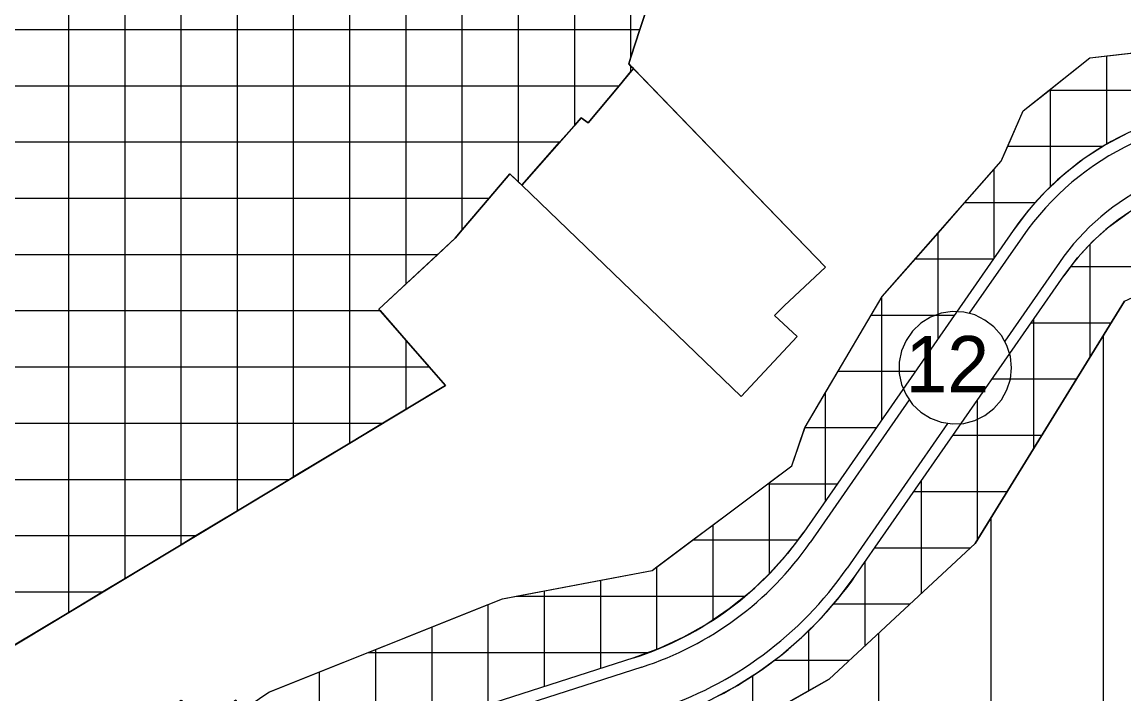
# Model space of a CAD drawing. Extents: x 427903 to 430077, y 4477233 to 4480385.
# Drawn here: x 428612.6 to 428808.6, y 4478205.3 to 4478324.8 of the extents above; entities that cross this region are included whole.
import ezdxf

# ---------------------------------------------------------------- set-up
doc = ezdxf.new("R2010")
doc.units = 0
for name, color, linetype in [('ADAKENARI', 7, 'Continuous'), ('KALDIRIM', 7, 'Continuous'), ('KD_DAIRE', 7, 'Continuous'), ('KD_YGEN', 7, 'Continuous'), ('PL_K_TALI_IS_MRK', 7, 'Continuous'), ('PL_KON_MEV_150', 7, 'Continuous'), ('TR_AZYOGUNKONUT', 7, 'Continuous'), ('TR_TALIISMERK', 7, 'Continuous')]:
    doc.layers.add(name, color=color, linetype=linetype)

msp = doc.modelspace()

# ---------------------------------------------------------------- linework, layer by layer
at = {"layer": 'ADAKENARI'}
for p, q in [((428720.56, 4478317.36), (428723.39, 4478326.12)), ((428802.55, 4478318.43), (428834.94, 4478322.18)), ((428790.72, 4478309), (428802.55, 4478318.43)), ((428786.8, 4478300.04), (428790.72, 4478309)), ((428765.63, 4478276), (428786.8, 4478300.04)), ((428689.68, 4478286.36), (428699.4, 4478297.83)), ((428788.92, 4478287.75), (428751.66, 4478234.1)), ((428676.08, 4478273.76), (428689.68, 4478286.36)), ((428761.02, 4478226.54), (428797.91, 4478279.65)), ((428751.92, 4478252.77), (428765.63, 4478276)), ((428782.14, 4478232.07), (428808.75, 4478275.19)), ((428687.94, 4478260.16), (428676.08, 4478273.76)), ((428607.7, 4478211.85), (428687.94, 4478260.16)), ((428749.55, 4478245.88), (428751.92, 4478252.77)), ((428724.7, 4478227.25), (428749.55, 4478245.88)), ((428756.17, 4478207.92), (428782.14, 4478232.07)), ((428698.11, 4478222.24), (428724.7, 4478227.25)), ((428656.5, 4478205.63), (428698.11, 4478222.24)), ((428721.45, 4478211.74), (428689.92, 4478201.62)), ((428705.03, 4478179.04), (428756.17, 4478207.92)), ((428651.53, 4478202.28), (428656.5, 4478205.63))]:
    msp.add_line(p, q, dxfattribs=at)
for points in [[(428721.36, 4478316.53), (428713.35, 4478306.89), (428712.09, 4478307.75), (428701.51, 4478295.79)], [(428740.52, 4478258.21), (428750.51, 4478268.87), (428746.45, 4478272.6), (428748.19, 4478274.33), (428755.53, 4478281.23), (428720.56, 4478317.36)], [(428740.52, 4478258.21), (428701.51, 4478295.79), (428699.4, 4478297.83)]]:
    msp.add_lwpolyline(points, dxfattribs=at)
for centre, radius, start, end in [((428831.63, 4478258.09), 52, 85.5155, 145.2166), ((428832.95, 4478255.31), 42.66, 85.5155, 145.2166), ((428703.55, 4478267.52), 58.58, 287.792, 325.2166), ((428705.17, 4478265.33), 68, 287.792, 325.2166)]:
    msp.add_arc(centre, radius, start, end, dxfattribs=at)
at = {"layer": 'KALDIRIM'}
for p, q in [((428790.57, 4478286.61), (428781.12, 4478273.01)), ((428797.14, 4478282.04), (428787.43, 4478268.07)), ((428770.42, 4478257.61), (428752.8, 4478232.24)), ((428777.26, 4478253.42), (428759.37, 4478227.68)), ((428722.89, 4478210.11), (428690.36, 4478199.67))]:
    msp.add_line(p, q, dxfattribs=at)
for centre, radius, start, end in [((428831.63, 4478258.09), 50, 85.5155, 145.2166), ((428831.63, 4478258.09), 42, 85.5155, 145.2166), ((428705.17, 4478265.33), 58, 287.792, 325.2166), ((428705.17, 4478265.33), 66, 287.792, 325.2166)]:
    msp.add_arc(centre, radius, start, end, dxfattribs=at)
at = {"layer": 'KD_DAIRE'}
for p, q in [((428776.12, 4478273.01), (428774.22, 4478272.31)), ((428776.12, 4478273.01), (428774.22, 4478272.31)), ((428778.12, 4478273.32), (428776.12, 4478273.01)), ((428778.12, 4478273.32), (428776.12, 4478273.01)), ((428780.14, 4478273.21), (428778.12, 4478273.32)), ((428780.14, 4478273.21), (428778.12, 4478273.32)), ((428782.1, 4478272.71), (428780.14, 4478273.21)), ((428782.1, 4478272.71), (428780.14, 4478273.21)), ((428772.5, 4478271.24), (428771.04, 4478269.84)), ((428772.5, 4478271.24), (428771.04, 4478269.84)), ((428774.22, 4478272.31), (428772.5, 4478271.24)), ((428774.22, 4478272.31), (428772.5, 4478271.24)), ((428783.91, 4478271.81), (428782.1, 4478272.71)), ((428783.91, 4478271.81), (428782.1, 4478272.71)), ((428785.51, 4478270.58), (428783.91, 4478271.81)), ((428785.51, 4478270.58), (428783.91, 4478271.81)), ((428771.04, 4478269.84), (428769.88, 4478268.18)), ((428771.04, 4478269.84), (428769.88, 4478268.18)), ((428786.83, 4478269.04), (428785.51, 4478270.58)), ((428786.83, 4478269.04), (428785.51, 4478270.58)), ((428769.88, 4478268.18), (428769.08, 4478266.32)), ((428769.88, 4478268.18), (428769.08, 4478266.32)), ((428787.81, 4478267.27), (428786.83, 4478269.04)), ((428787.81, 4478267.27), (428786.83, 4478269.04)), ((428788.42, 4478265.34), (428787.81, 4478267.27)), ((428788.42, 4478265.34), (428787.81, 4478267.27)), ((428769.08, 4478266.32), (428768.67, 4478264.34)), ((428769.08, 4478266.32), (428768.67, 4478264.34)), ((428788.62, 4478263.33), (428788.42, 4478265.34)), ((428788.62, 4478263.33), (428788.42, 4478265.34)), ((428768.67, 4478264.34), (428768.67, 4478262.32)), ((428768.67, 4478264.34), (428768.67, 4478262.32)), ((428788.42, 4478261.32), (428788.62, 4478263.33)), ((428788.42, 4478261.32), (428788.62, 4478263.33)), ((428788.62, 4478263.33), (428788.62, 4478263.33)), ((428788.62, 4478263.33), (428788.62, 4478263.33)), ((428768.67, 4478262.32), (428769.08, 4478260.33)), ((428768.67, 4478262.32), (428769.08, 4478260.33)), ((428787.81, 4478259.38), (428788.42, 4478261.32)), ((428787.81, 4478259.38), (428788.42, 4478261.32)), ((428769.08, 4478260.33), (428769.88, 4478258.48)), ((428769.08, 4478260.33), (428769.88, 4478258.48)), ((428786.83, 4478257.62), (428787.81, 4478259.38)), ((428786.83, 4478257.62), (428787.81, 4478259.38)), ((428769.88, 4478258.48), (428771.04, 4478256.81)), ((428769.88, 4478258.48), (428771.04, 4478256.81)), ((428785.51, 4478256.08), (428786.83, 4478257.62)), ((428785.51, 4478256.08), (428786.83, 4478257.62)), ((428771.04, 4478256.81), (428772.5, 4478255.42)), ((428771.04, 4478256.81), (428772.5, 4478255.42)), ((428772.5, 4478255.42), (428774.22, 4478254.35)), ((428772.5, 4478255.42), (428774.22, 4478254.35)), ((428783.91, 4478254.84), (428785.51, 4478256.08)), ((428783.91, 4478254.84), (428785.51, 4478256.08)), ((428774.22, 4478254.35), (428776.12, 4478253.65)), ((428774.22, 4478254.35), (428776.12, 4478253.65)), ((428776.12, 4478253.65), (428778.12, 4478253.34)), ((428776.12, 4478253.65), (428778.12, 4478253.34)), ((428778.12, 4478253.34), (428780.14, 4478253.44)), ((428778.12, 4478253.34), (428780.14, 4478253.44)), ((428780.14, 4478253.44), (428782.1, 4478253.95)), ((428780.14, 4478253.44), (428782.1, 4478253.95)), ((428782.1, 4478253.95), (428783.91, 4478254.84)), ((428782.1, 4478253.95), (428783.91, 4478254.84))]:
    msp.add_line(p, q, dxfattribs=at)
at = {"layer": 'PL_K_TALI_IS_MRK'}
for points in [[(428720.94, 4478318.54), (428722.53, 4478323.48), (428723.39, 4478326.12)], [(428723.39, 4478326.12), (428722.53, 4478323.48)], [(428585.56, 4478161.55), (428622.82, 4478193.45), (428640.91, 4478204.24), (428644.71, 4478199.71), (428650.67, 4478204.26), (428651.53, 4478202.28), (428656.5, 4478205.63), (428698.11, 4478222.24), (428724.7, 4478227.25), (428749.55, 4478245.88), (428751.92, 4478252.77), (428765.63, 4478276), (428786.8, 4478300.04), (428790.72, 4478309), (428802.55, 4478318.43), (428834.94, 4478322.18), (428855.63, 4478318.81), (428872.14, 4478313.5), (428933.8, 4478304.14), (429004.02, 4478272.11)], [(428722.53, 4478323.48), (428720.94, 4478318.54), (428720.56, 4478317.36), (428720.94, 4478316.97), (428721.36, 4478316.53), (428755.53, 4478281.23), (428748.19, 4478274.33), (428746.45, 4478272.6), (428750.51, 4478268.87), (428740.52, 4478258.21), (428701.51, 4478295.79), (428700.94, 4478296.34), (428699.4, 4478297.83), (428695.71, 4478293.48), (428690.94, 4478287.85), (428689.68, 4478286.36), (428686.57, 4478283.48), (428680.94, 4478278.26), (428676.08, 4478273.76), (428676.32, 4478273.48), (428680.94, 4478268.18), (428685.04, 4478263.48), (428687.94, 4478260.16), (428680.94, 4478255.95), (428676.83, 4478253.48), (428670.94, 4478249.93), (428660.94, 4478243.91), (428660.22, 4478243.48), (428650.94, 4478237.89), (428643.62, 4478233.48), (428640.94, 4478231.86), (428630.94, 4478225.84), (428627.01, 4478223.48), (428620.94, 4478219.82), (428610.94, 4478213.8)], [(428610.94, 4478213.8), (428620.94, 4478219.82), (428627.01, 4478223.48), (428630.94, 4478225.84), (428640.94, 4478231.86), (428643.62, 4478233.48), (428650.94, 4478237.89), (428660.22, 4478243.48), (428660.94, 4478243.91), (428670.94, 4478249.93), (428676.83, 4478253.48), (428680.94, 4478255.95), (428687.94, 4478260.16), (428685.04, 4478263.48), (428680.94, 4478268.18), (428676.32, 4478273.48), (428676.08, 4478273.76), (428680.94, 4478278.26), (428686.57, 4478283.48), (428689.68, 4478286.36), (428690.94, 4478287.85), (428695.71, 4478293.48), (428699.4, 4478297.83), (428700.94, 4478296.34), (428701.51, 4478295.79), (428708.31, 4478303.48), (428710.94, 4478306.45), (428712.09, 4478307.75), (428713.35, 4478306.89), (428718.82, 4478313.48), (428720.94, 4478316.03), (428721.36, 4478316.53), (428720.94, 4478316.97), (428720.56, 4478317.36), (428720.94, 4478318.54)], [(428655.56, 4478205), (428656.5, 4478205.63), (428665.56, 4478209.25), (428674.2, 4478212.7), (428675.56, 4478213.24), (428685.56, 4478217.23), (428695.56, 4478221.22), (428698.11, 4478222.24), (428700.53, 4478222.7), (428705.56, 4478223.65), (428715.56, 4478225.53), (428724.7, 4478227.25), (428725.56, 4478227.9), (428731.96, 4478232.7), (428735.56, 4478235.4), (428745.3, 4478242.7), (428745.56, 4478242.9), (428749.55, 4478245.88), (428751.89, 4478252.7), (428751.92, 4478252.77), (428755.56, 4478258.95), (428757.77, 4478262.7), (428763.68, 4478272.7), (428765.56, 4478275.89), (428765.63, 4478276), (428771.52, 4478282.7), (428775.56, 4478287.28), (428780.33, 4478292.7), (428785.56, 4478298.64), (428786.8, 4478300.04), (428787.96, 4478302.7), (428790.72, 4478309), (428795.36, 4478312.7), (428795.56, 4478312.86), (428802.55, 4478318.43), (428805.56, 4478318.78), (428815.56, 4478319.94)], [(428708.31, 4478303.48), (428701.51, 4478295.79), (428740.52, 4478258.21), (428750.51, 4478268.87), (428746.45, 4478272.6), (428748.19, 4478274.33), (428755.53, 4478281.23), (428721.36, 4478316.53), (428720.94, 4478316.03), (428718.82, 4478313.48), (428713.35, 4478306.89), (428712.09, 4478307.75), (428710.94, 4478306.45), (428708.31, 4478303.48)], [(428809.35, 4478305.07), (428805.36, 4478302.96), (428801.57, 4478300.51), (428798, 4478297.75), (428794.69, 4478294.68), (428791.66, 4478291.34), (428788.92, 4478287.75), (428751.66, 4478234.1), (428748.77, 4478230.29), (428745.59, 4478226.72), (428742.12, 4478223.43), (428738.4, 4478220.43), (428734.44, 4478217.75), (428730.28, 4478215.39), (428725.94, 4478213.39), (428721.45, 4478211.74), (428689.92, 4478201.62)], [(428735.09, 4478204.27), (428739.44, 4478206.6), (428743.61, 4478209.24), (428747.58, 4478212.18), (428751.32, 4478215.39), (428754.82, 4478218.87), (428758.06, 4478222.59), (428761.02, 4478226.54), (428797.91, 4478279.65), (428800.37, 4478282.85), (428803.12, 4478285.81), (428806.13, 4478288.5), (428809.39, 4478290.88)], [(428808.75, 4478275.19), (428782.14, 4478232.07), (428756.17, 4478207.92), (428705.03, 4478179.04)]]:
    msp.add_lwpolyline(points, dxfattribs=at)
at = {"layer": 'PL_KON_MEV_150'}
msp.add_lwpolyline([(428917.5, 4478262.42), (428936.22, 4478235.59), (428952.23, 4478189.67), (428913.06, 4478170.27), (428903.17, 4478189.83), (428868.79, 4478175.38), (428861.18, 4478187.2), (428842.96, 4478177.3), (428835.68, 4478188.79), (428792.13, 4478162.34), (428775.21, 4478183.31), (428756.95, 4478169.39), (428745.68, 4478184.6), (428716.29, 4478165.07), (428705, 4478178.94), (428705.03, 4478179.04), (428756.17, 4478207.92), (428782.14, 4478232.07), (428808.75, 4478275.19), (428825.08, 4478282.72), (428861.7, 4478285.08), (428887.4, 4478280.32)], close=True, dxfattribs=at)
at = {"layer": 'TR_AZYOGUNKONUT'}
for p, q in [((428805, 4478170.16), (428805, 4478269.12)), ((428785, 4478171.17), (428785, 4478236.71)), ((428765, 4478175.53), (428765, 4478216.14))]:
    msp.add_line(p, q, dxfattribs=at)
at = {"layer": 'TR_TALIISMERK'}
for p, q in [((428720.94, 4478318.54), (428720.94, 4478427.11)), ((428710.94, 4478306.45), (428710.94, 4478421.21)), ((428700.94, 4478296.34), (428700.94, 4478414.79)), ((428690.94, 4478287.85), (428690.94, 4478407.98)), ((428680.94, 4478278.26), (428680.94, 4478401.14)), ((428670.94, 4478249.93), (428670.94, 4478394.29)), ((428660.94, 4478243.91), (428660.94, 4478387.55)), ((428650.94, 4478237.89), (428650.94, 4478381.81)), ((428640.94, 4478231.86), (428640.94, 4478377.31)), ((428630.94, 4478225.84), (428630.94, 4478373.99)), ((428620.94, 4478219.82), (428620.94, 4478371.62)), ((428518.79, 4478323.48), (428722.53, 4478323.48)), ((428805.56, 4478303.07), (428805.56, 4478318.78)), ((428720.94, 4478316.03), (428720.94, 4478316.97)), ((428513.83, 4478313.48), (428718.82, 4478313.48)), ((428795.36, 4478312.7), (428877.41, 4478312.7)), ((428795.56, 4478295.49), (428795.56, 4478312.86)), ((428508.86, 4478303.48), (428708.31, 4478303.48)), ((428787.96, 4478302.7), (428804.95, 4478302.7)), ((428785.56, 4478282.91), (428785.56, 4478298.64)), ((428503.89, 4478293.48), (428695.71, 4478293.48)), ((428780.33, 4478292.7), (428792.89, 4478292.7)), ((428775.56, 4478268.51), (428775.56, 4478287.28)), ((428802.59, 4478265.2), (428802.59, 4478285.24)), ((428498.69, 4478283.48), (428686.57, 4478283.48)), ((428771.52, 4478282.7), (428785.41, 4478282.7)), ((428799.2, 4478281.33), (428822.07, 4478281.33)), ((428765.56, 4478254.12), (428765.56, 4478275.89)), ((428492.58, 4478273.48), (428676.32, 4478273.48)), ((428763.68, 4478272.7), (428778.47, 4478272.7)), ((428792.13, 4478271.33), (428806.37, 4478271.33)), ((428792.59, 4478249), (428792.59, 4478271.99)), ((428680.94, 4478255.95), (428680.94, 4478268.18)), ((428485.49, 4478263.48), (428685.04, 4478263.48)), ((428757.77, 4478262.7), (428771.52, 4478262.7)), ((428785.18, 4478261.33), (428800.2, 4478261.33)), ((428755.56, 4478239.72), (428755.56, 4478258.95)), ((428782.59, 4478232.79), (428782.59, 4478257.59)), ((428477.13, 4478253.48), (428676.83, 4478253.48)), ((428751.89, 4478252.7), (428764.58, 4478252.7)), ((428778.24, 4478251.33), (428794.02, 4478251.33)), ((428467.37, 4478243.48), (428660.22, 4478243.48)), ((428745.3, 4478242.7), (428757.63, 4478242.7)), ((428745.56, 4478226.7), (428745.56, 4478242.9)), ((428772.59, 4478223.19), (428772.59, 4478243.2)), ((428771.29, 4478241.33), (428787.85, 4478241.33)), ((428735.56, 4478218.51), (428735.56, 4478235.4)), ((428455.86, 4478233.48), (428643.62, 4478233.48)), ((428731.96, 4478232.7), (428750.6, 4478232.7)), ((428764.34, 4478231.33), (428781.34, 4478231.33)), ((428725.56, 4478213.25), (428725.56, 4478227.9)), ((428762.59, 4478213.89), (428762.59, 4478228.8)), ((428715.56, 4478209.85), (428715.56, 4478225.53)), ((428444.01, 4478223.48), (428627.01, 4478223.48)), ((428700.53, 4478222.7), (428741.21, 4478222.7)), ((428705.56, 4478206.64), (428705.56, 4478223.65)), ((428695.56, 4478203.44), (428695.56, 4478221.22)), ((428756.96, 4478221.33), (428770.58, 4478221.33)), ((428685.56, 4478200.3), (428685.56, 4478217.23)), ((428752.59, 4478205.9), (428752.59, 4478216.65)), ((428674.2, 4478212.7), (428724.05, 4478212.7)), ((428675.56, 4478197.68), (428675.56, 4478213.24)), ((428746.43, 4478211.33), (428759.83, 4478211.33)), ((428665.56, 4478195.67), (428665.56, 4478209.25)), ((428742.59, 4478200.25), (428742.59, 4478208.59))]:
    msp.add_line(p, q, dxfattribs=at)
for points in [[(428723.39, 4478326.12), (428722.53, 4478323.48)], [(428722.53, 4478323.48), (428720.94, 4478318.54), (428720.56, 4478317.36), (428720.94, 4478316.97), (428721.36, 4478316.53), (428755.53, 4478281.23), (428748.19, 4478274.33), (428746.45, 4478272.6), (428750.51, 4478268.87), (428740.52, 4478258.21), (428701.51, 4478295.79), (428700.94, 4478296.34), (428699.4, 4478297.83), (428695.71, 4478293.48), (428690.94, 4478287.85), (428689.68, 4478286.36), (428686.57, 4478283.48), (428680.94, 4478278.26), (428676.08, 4478273.76), (428676.32, 4478273.48), (428680.94, 4478268.18), (428685.04, 4478263.48), (428687.94, 4478260.16), (428680.94, 4478255.95), (428676.83, 4478253.48), (428670.94, 4478249.93), (428660.94, 4478243.91), (428660.22, 4478243.48), (428650.94, 4478237.89), (428643.62, 4478233.48), (428640.94, 4478231.86), (428630.94, 4478225.84), (428627.01, 4478223.48), (428620.94, 4478219.82), (428610.94, 4478213.8)], [(428655.56, 4478205), (428656.5, 4478205.63), (428665.56, 4478209.25), (428674.2, 4478212.7), (428675.56, 4478213.24), (428685.56, 4478217.23), (428695.56, 4478221.22), (428698.11, 4478222.24), (428700.53, 4478222.7), (428705.56, 4478223.65), (428715.56, 4478225.53), (428724.7, 4478227.25), (428725.56, 4478227.9), (428731.96, 4478232.7), (428735.56, 4478235.4), (428745.3, 4478242.7), (428745.56, 4478242.9), (428749.55, 4478245.88), (428751.89, 4478252.7), (428751.92, 4478252.77), (428755.56, 4478258.95), (428757.77, 4478262.7), (428763.68, 4478272.7), (428765.56, 4478275.89), (428765.63, 4478276), (428771.52, 4478282.7), (428775.56, 4478287.28), (428780.33, 4478292.7), (428785.56, 4478298.64), (428786.8, 4478300.04), (428787.96, 4478302.7), (428790.72, 4478309), (428795.36, 4478312.7), (428795.56, 4478312.86), (428802.55, 4478318.43), (428805.56, 4478318.78), (428815.56, 4478319.94)], [(428712.09, 4478307.75), (428710.94, 4478306.45), (428708.31, 4478303.48), (428701.51, 4478295.79), (428740.52, 4478258.21), (428750.51, 4478268.87), (428746.45, 4478272.6), (428748.19, 4478274.33), (428755.53, 4478281.23), (428721.36, 4478316.53), (428720.94, 4478316.03), (428718.82, 4478313.48), (428713.35, 4478306.89), (428712.09, 4478307.75)]]:
    msp.add_lwpolyline(points, dxfattribs=at)

# ---------------------------------------------------------------- texts
at = {"layer": 'KD_YGEN'}
msp.add_text('12', height=10, dxfattribs=at).set_placement((428769.77, 4478258.97))

doc.saveas('drawing.dxf')
